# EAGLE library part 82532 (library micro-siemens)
MICROPROCESSOR/PERIPHERAL DEVICE
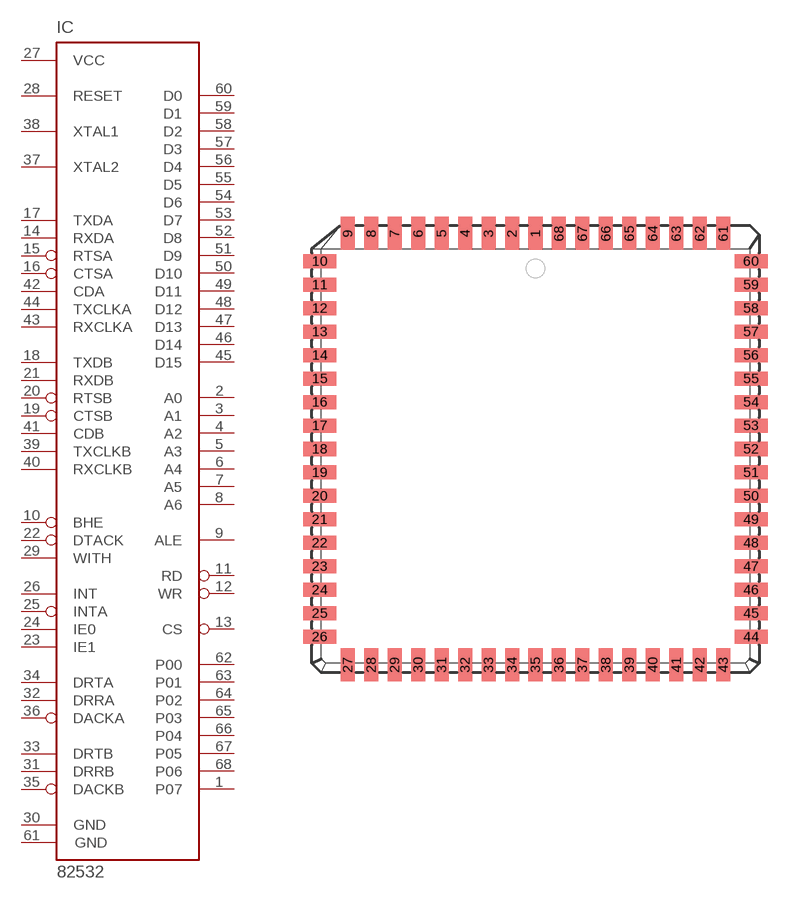
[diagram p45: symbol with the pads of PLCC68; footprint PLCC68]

Designator prefix IC

## 82532 (OC_FARNELL: unknown; OC_NEWARK: unknown)  [PLCC68]
1  P07
2  A0  in
3  A1  in
4  A2  in
5  A3  in
6  A4  in
7  A5  in
8  A6  in
9  ALE  in
10  BHE  in
11  RD  in
12  WR  in
13  CS  in
14  RXDA
15  RTSA  out
16  CTSA  in
17  TXDA
18  TXDB
19  CTSB  in
20  RTSB  out
21  RXDB
22  DTACK  out
23  IE1  in
24  IE0
25  INTA  in
26  INT  out
27  VCC  pwr
28  RESET  in
29  WITH  in
30  GND  pwr
31  DRRB  out
32  DRRA  out
33  DRTB  out
34  DRTA  out
35  DACKB  in
36  DACKA  in
37  XTAL2  pas
38  XTAL1  pas
39  TXCLKB
40  RXCLKB  in
41  CDB  in
42  CDA  in
43  RXCLKA  in
44  TXCLKA
45  D15
46  D14
47  D13
48  D12
49  D11
50  D10
51  D9
52  D8
53  D7
54  D6
55  D5
56  D4
57  D3
58  D2
59  D1
60  D0
61  GND  pwr
62  P00
63  P01
64  P02
65  P03
66  P04
67  P05
68  P06

## Footprint PLCC68 (pad centres in mm)
PLASTIC LEADED CHIP CARRIER square
smd 0.76 x 1.8: 1 0,11.67; 2 -1.27,11.67; 3 -2.54,11.67; 4 -3.81,11.67; 5 -5.08,11.67; 6 -6.35,11.67; 7 -7.62,11.67; 8 -8.89,11.67; 9 -10.16,11.67; 27 -10.16,-11.67; 28 -8.89,-11.67; 29 -7.62,-11.67; 30 -6.35,-11.67; 31 -5.08,-11.67; 32 -3.81,-11.67; 33 -2.54,-11.67; 34 -1.27,-11.67; 35 0,-11.67; 36 1.27,-11.67; 37 2.54,-11.67; 38 3.81,-11.67; 39 5.08,-11.67; 40 6.35,-11.67; 41 7.62,-11.67; 42 8.89,-11.67; 43 10.16,-11.67; 61 10.16,11.67; 62 8.89,11.67; 63 7.62,11.67; 64 6.35,11.67; 65 5.08,11.67; 66 3.81,11.67; 67 2.54,11.67; 68 1.27,11.67
smd 1.8 x 0.76: 10 -11.67,10.16; 11 -11.67,8.89; 12 -11.67,7.62; 13 -11.67,6.35; 14 -11.67,5.08; 15 -11.67,3.81; 16 -11.67,2.54; 17 -11.67,1.27; 18 -11.67,0; 19 -11.67,-1.27; 20 -11.67,-2.54; 21 -11.67,-3.81; 22 -11.67,-5.08; 23 -11.67,-6.35; 24 -11.67,-7.62; 25 -11.67,-8.89; 26 -11.67,-10.16; 44 11.67,-10.16; 45 11.67,-8.89; 46 11.67,-7.62; 47 11.67,-6.35; 48 11.67,-5.08; 49 11.67,-3.81; 50 11.67,-2.54; 51 11.67,-1.27; 52 11.67,0; 53 11.67,1.27; 54 11.67,2.54; 55 11.67,3.81; 56 11.67,5.08; 57 11.67,6.35; 58 11.67,7.62; 59 11.67,8.89; 60 11.67,10.16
